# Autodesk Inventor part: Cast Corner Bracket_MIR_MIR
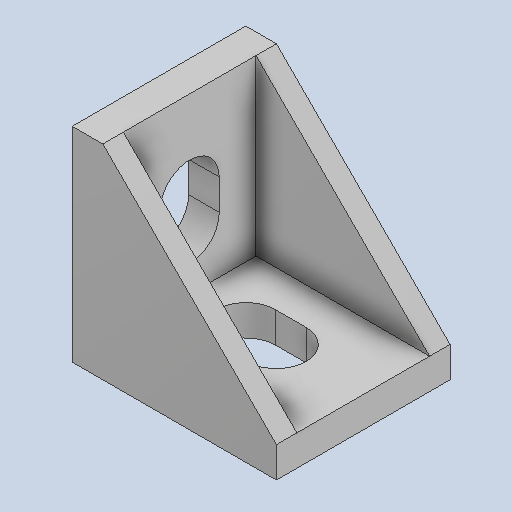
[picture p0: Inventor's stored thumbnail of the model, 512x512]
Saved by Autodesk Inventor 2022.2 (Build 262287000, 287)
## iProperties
Created: 2019-09
Part Number: Cast Corner Bracket_MIR_MIR
Material: SolidWorks Materials|6061-T6 (SS)
Document SubType Name: Modeling
Designer: 18907419
Density: 2.7 g/cm^3
Appearance: Default
Author: 18907419
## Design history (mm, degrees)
feature "Solido1"
node "Solido2"
